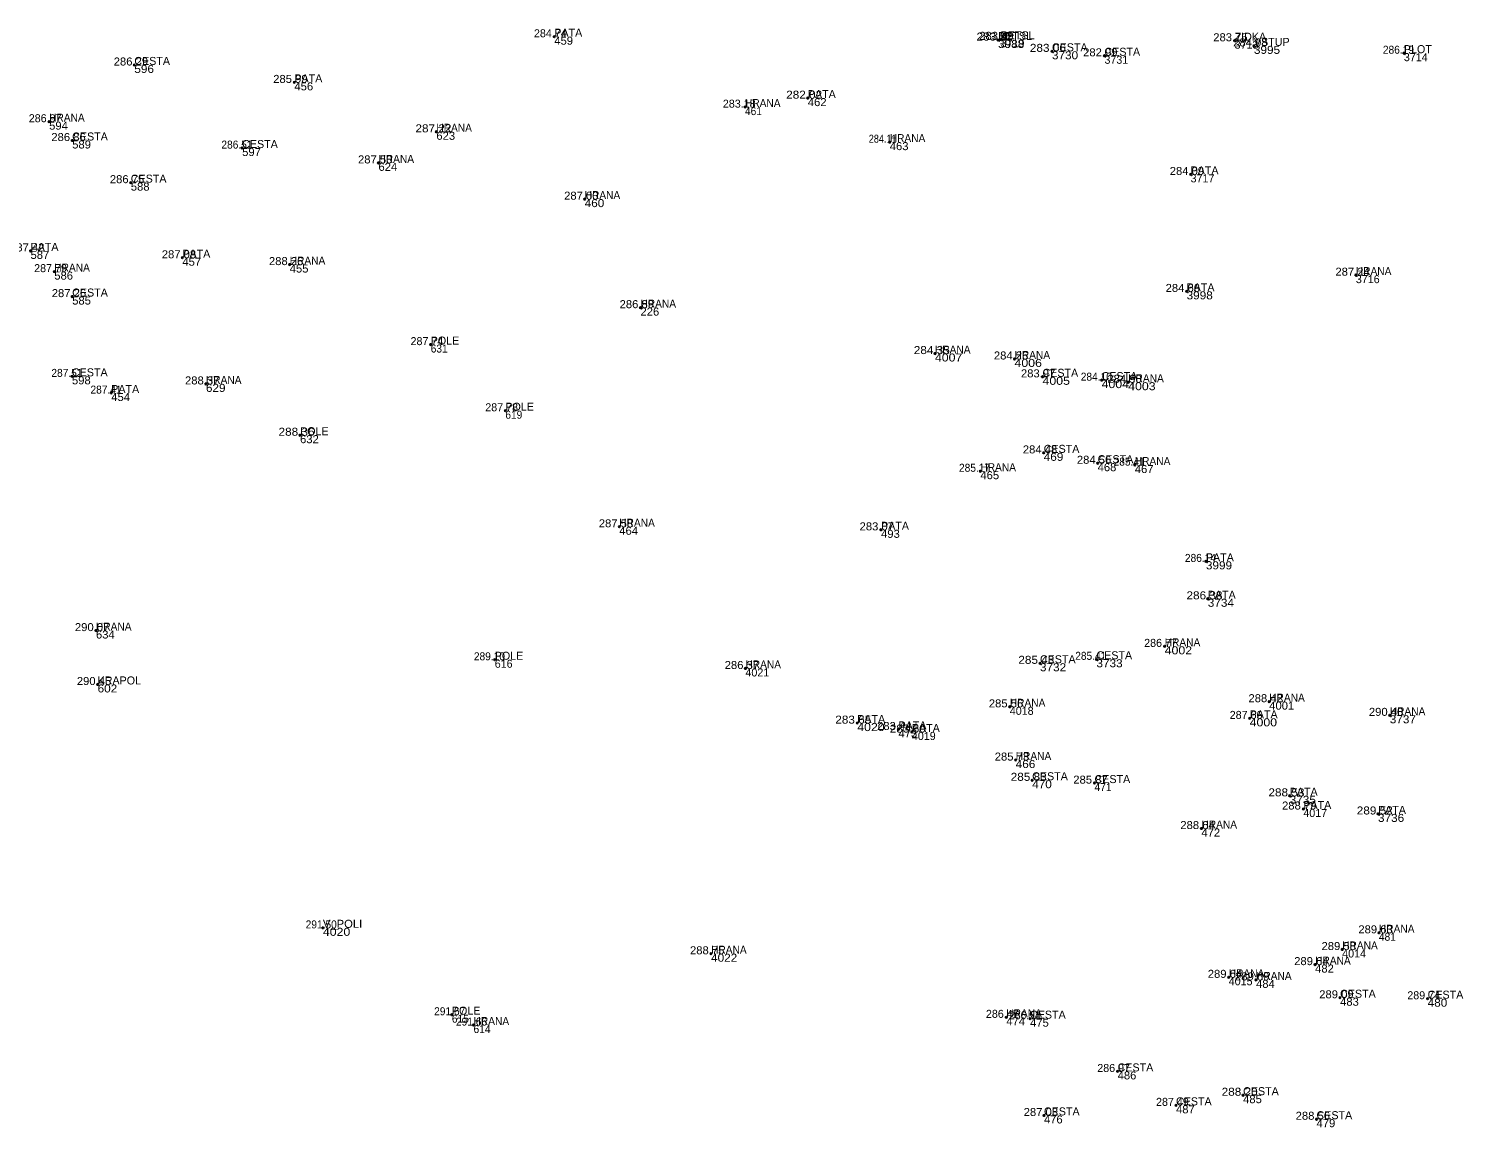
# Model space of a CAD drawing. Extents: x -565336 to -561834, y -1146819 to -1145270.
# Drawn here: x -563681.7 to -563620.8, y -1145851.4 to -1145804.8 of the extents above; entities that cross this region are included whole.
import ezdxf
from ezdxf.enums import TextEntityAlignment as Align

# ---------------------------------------------------------------- set-up
doc = ezdxf.new("R2010")
doc.units = 0
doc.header["$LTSCALE"] = 0.14
doc.header["$PDMODE"] = 32
doc.header["$PDSIZE"] = 0.07
for name, color, linetype in [('40', 7, 'Continuous'), ('43', 7, 'Continuous'), ('44', 7, 'Continuous'), ('45', 7, 'Continuous')]:
    doc.layers.add(name, color=color, linetype=linetype)

msp = doc.modelspace()

# ---------------------------------------------------------------- linework, layer by layer
at = {"layer": '40'}
for p in [(-563659.39, -1145805.09), (-563640.54, -1145805.23), (-563640.43, -1145805.2), (-563630.49, -1145805.26), (-563638.25, -1145805.71), (-563636.02, -1145805.9), (-563629.67, -1145805.48), (-563623.3, -1145805.79), (-563677.23, -1145806.29), (-563670.43, -1145807.03), (-563648.62, -1145807.7), (-563651.29, -1145808.08), (-563680.85, -1145808.7), (-563679.87, -1145809.5), (-563664.4, -1145809.13), (-563645.14, -1145809.57), (-563672.65, -1145809.82), (-563666.86, -1145810.45), (-563677.38, -1145811.29), (-563632.36, -1145810.94), (-563658.1, -1145811.99), (-563681.64, -1145814.19), (-563675.19, -1145814.48), (-563680.63, -1145815.07), (-563670.63, -1145814.77), (-563625.34, -1145815.22), (-563679.87, -1145816.13), (-563632.53, -1145815.91), (-563655.73, -1145816.6), (-563664.64, -1145818.17), (-563643.22, -1145818.55), (-563639.84, -1145818.78), (-563679.88, -1145819.52), (-563674.19, -1145819.84), (-563638.65, -1145819.54), (-563636.14, -1145819.68), (-563635.01, -1145819.77), (-563678.21, -1145820.23), (-563661.47, -1145820.98), (-563670.19, -1145822.02), (-563638.6, -1145822.77), (-563641.29, -1145823.55), (-563636.31, -1145823.21), (-563634.73, -1145823.29), (-563656.63, -1145825.91), (-563645.51, -1145826.04), (-563631.71, -1145827.38), (-563631.63, -1145828.97), (-563678.86, -1145830.32), (-563661.92, -1145831.56), (-563636.36, -1145831.54), (-563633.46, -1145830.99), (-563651.27, -1145831.93), (-563638.76, -1145831.71), (-563678.79, -1145832.61), (-563629.02, -1145833.34), (-563640.04, -1145833.56), (-563623.9, -1145833.92), (-563646.52, -1145834.25), (-563644.77, -1145834.52), (-563644.2, -1145834.63), (-563629.85, -1145834.05), (-563639.79, -1145835.82), (-563639.09, -1145836.68), (-563636.44, -1145836.8), (-563628.15, -1145837.34), (-563627.57, -1145837.9), (-563624.4, -1145838.11), (-563631.9, -1145838.73), (-563669.22, -1145842.95), (-563624.36, -1145843.16), (-563652.73, -1145844.05), (-563625.92, -1145843.87), (-563627.07, -1145844.51), (-563630.74, -1145845.05), (-563629.58, -1145845.16), (-563626.01, -1145845.92), (-563622.29, -1145845.96), (-563663.74, -1145846.64), (-563640.19, -1145846.75), (-563639.18, -1145846.81), (-563662.82, -1145847.08), (-563635.46, -1145849.05), (-563630.13, -1145850.06), (-563638.59, -1145850.92), (-563632.98, -1145850.49), (-563627.01, -1145851.08)]:
    msp.add_point(p, dxfattribs=at)

# ---------------------------------------------------------------- texts
at = {"layer": '43'}
for s, width, p in [('459', 1.05, (-563659.39, -1145805.43)), ('3988', 1.1, (-563640.54, -1145805.57)), ('3730', 1.1, (-563638.25, -1145806.05)), ('3995', 1.1, (-563629.67, -1145805.82)), ('596', 1.1, (-563677.23, -1145806.63)), ('456', 1.05, (-563670.43, -1145807.37)), ('462', 1.05, (-563648.62, -1145808.04)), ('461', 0.95, (-563651.29, -1145808.42)), ('594', 1.05, (-563680.85, -1145809.04)), ('589', 1.05, (-563679.87, -1145809.84)), ('623', 1.05, (-563664.4, -1145809.47)), ('463', 1.05, (-563645.14, -1145809.91)), ('597', 1.05, (-563672.65, -1145810.16)), ('624', 1.05, (-563666.86, -1145810.79)), ('588', 1.05, (-563677.38, -1145811.63)), ('460', 1.1, (-563658.1, -1145812.33)), ('587', 1.05, (-563681.64, -1145814.53)), ('457', 1.05, (-563675.19, -1145814.82)), ('586', 1.05, (-563680.63, -1145815.41)), ('455', 1.05, (-563670.63, -1145815.11)), ('585', 1.05, (-563679.87, -1145816.47)), ('3998', 1.1, (-563632.53, -1145816.25)), ('226', 1.05, (-563655.73, -1145816.94)), ('631', 0.95, (-563664.64, -1145818.51)), ('4007', 1.15, (-563643.22, -1145818.89)), ('4006', 1.15, (-563639.84, -1145819.12)), ('598', 1.05, (-563679.88, -1145819.86)), ('629', 1.1, (-563674.19, -1145820.18)), ('4005', 1.15, (-563638.65, -1145819.88)), ('4004', 1.15, (-563636.14, -1145820.02)), ('4003', 1.15, (-563635.01, -1145820.11)), ('454', 1.05, (-563678.21, -1145820.57)), ('619', 0.95, (-563661.47, -1145821.32)), ('632', 1.05, (-563670.19, -1145822.36)), ('469', 1.1, (-563638.6, -1145823.11)), ('465', 1.05, (-563641.29, -1145823.89)), ('468', 1.05, (-563636.31, -1145823.55)), ('467', 1.05, (-563634.73, -1145823.63)), ('464', 1.05, (-563656.63, -1145826.25)), ('493', 1.05, (-563645.51, -1145826.38)), ('3999', 1.1, (-563631.71, -1145827.72)), ('3734', 1.1, (-563631.63, -1145829.31)), ('634', 1.05, (-563678.86, -1145830.66)), ('3733', 1.1, (-563636.36, -1145831.88)), ('4002', 1.15, (-563633.46, -1145831.33)), ('3732', 1.1, (-563638.76, -1145832.05)), ('602', 1.1, (-563678.79, -1145832.95)), ('4001', 1.05, (-563629.02, -1145833.68)), ('3737', 1.1, (-563623.9, -1145834.26)), ('4020', 1.15, (-563646.52, -1145834.59)), ('473', 1.05, (-563644.77, -1145834.86)), ('4000', 1.15, (-563629.85, -1145834.39)), ('466', 1.1, (-563639.79, -1145836.16)), ('470', 1.1, (-563639.09, -1145837.02)), ('471', 0.95, (-563636.44, -1145837.14)), ('3735', 1.1, (-563628.15, -1145837.68)), ('3736', 1.1, (-563624.4, -1145838.45)), ('472', 1.05, (-563631.9, -1145839.07)), ('4020', 1.15, (-563669.22, -1145843.29)), ('481', 0.95, (-563624.36, -1145843.5)), ('4022', 1.1, (-563652.73, -1145844.39)), ('482', 1.05, (-563627.07, -1145844.85)), ('484', 1.05, (-563629.58, -1145845.5)), ('483', 1.05, (-563626.01, -1145846.26)), ('480', 1.1, (-563622.29, -1145846.3)), ('615', 0.95, (-563663.74, -1145846.98)), ('474', 1.05, (-563640.19, -1145847.09)), ('614', 0.95, (-563662.82, -1145847.42)), ('475', 1.05, (-563639.18, -1145847.15)), ('486', 1.05, (-563635.46, -1145849.39)), ('485', 1.05, (-563630.13, -1145850.4)), ('476', 1.05, (-563638.59, -1145851.26)), ('487', 1.05, (-563632.98, -1145850.83)), ('479', 1.05, (-563627.01, -1145851.42))]:
    msp.add_text(s, height=0.34, dxfattribs=dict(at, width=width)).set_placement(p)
for s, p in [('3719', (-563640.43, -1145805.54)), ('3713', (-563630.49, -1145805.6)), ('3731', (-563636.02, -1145806.24)), ('3714', (-563623.3, -1145806.13)), ('3717', (-563632.36, -1145811.28)), ('3716', (-563625.34, -1145815.56)), ('616', (-563661.92, -1145831.9)), ('4021', (-563651.27, -1145832.27)), ('4018', (-563640.04, -1145833.9)), ('4019', (-563644.2, -1145834.97)), ('4017', (-563627.57, -1145838.24)), ('4014', (-563625.92, -1145844.21)), ('4015', (-563630.74, -1145845.39))]:
    msp.add_text(s, height=0.34, dxfattribs=at).set_placement(p)
at = {"layer": '44'}
for s, p in [('284.74', (-563659.559, -1145805.114)), ('283.18', (-563651.534, -1145808.104)), ('286.97', (-563681.019, -1145808.724)), ('287.79', (-563680.791, -1145815.094)), ('287.74', (-563664.801, -1145818.194)), ('287.78', (-563661.627, -1145821.004)), ('286.77', (-563633.637, -1145831.014)), ('287.66', (-563630.0025, -1145834.074)), ('289.74', (-563622.459, -1145845.984)), ('286.47', (-563640.359, -1145846.774)), ('286.97', (-563635.629, -1145849.074)), ('287.49', (-563633.1325, -1145850.514))]:
    msp.add_text(s, height=0.34, dxfattribs=at).set_placement(p, align=Align.CENTER)
for s, width, p in [('283.22', 1.1, (-563640.689, -1145805.254)), ('283.49', 1.05, (-563640.608, -1145805.224)), ('283.75', 1.05, (-563630.667, -1145805.284)), ('284.08', 1.05, (-563629.8215, -1145805.504)), ('283.06', 1.1, (-563638.423, -1145805.734)), ('282.99', 1.05, (-563636.195, -1145805.924)), ('286.19', 0.95, (-563623.5305, -1145805.814)), ('286.29', 1.05, (-563677.376, -1145806.314)), ('285.99', 1.05, (-563670.6, -1145807.054)), ('282.02', 1.1, (-563648.775, -1145807.724)), ('287.22', 1.1, (-563664.5235, -1145809.154)), ('286.86', 1.05, (-563680.0255, -1145809.524)), ('286.51', 0.95, (-563672.871, -1145809.844)), ('284.11', 0.85, (-563645.44, -1145809.594)), ('287.50', 1.05, (-563666.998, -1145810.474)), ('284.09', 1.05, (-563632.5155, -1145810.964)), ('286.75', 1.05, (-563677.5395, -1145811.314)), ('287.00', 1.05, (-563658.242, -1145812.014)), ('287.42', 1.05, (-563681.778, -1145814.214)), ('287.08', 1.05, (-563675.3335, -1145814.504)), ('288.26', 1.05, (-563670.7815, -1145814.794)), ('287.24', 1.05, (-563625.478, -1145815.244)), ('284.66', 1.05, (-563632.6905, -1145815.934)), ('287.26', 1.05, (-563680.008, -1145816.154)), ('286.89', 1.05, (-563655.8855, -1145816.624)), ('284.35', 1.1, (-563643.354, -1145818.574)), ('284.26', 1.05, (-563639.986, -1145818.804)), ('287.51', 0.95, (-563680.093, -1145819.544)), ('283.97', 1.05, (-563638.8365, -1145819.564)), ('284.10', 0.95, (-563636.365, -1145819.704)), ('287.41', 0.95, (-563678.4325, -1145820.254)), ('288.37', 1.05, (-563674.347, -1145819.864)), ('284.90', 1.05, (-563635.1655, -1145819.794)), ('288.36', 1.1, (-563670.339, -1145822.044)), ('284.48', 1.05, (-563638.7565, -1145822.794)), ('284.56', 1.05, (-563636.4615, -1145823.234)), ('285.41', 0.95, (-563634.97, -1145823.314)), ('285.17', 0.95, (-563641.538, -1145823.574)), ('287.58', 1.05, (-563656.7695, -1145825.934)), ('283.07', 1.05, (-563645.691, -1145826.064)), ('286.14', 0.95, (-563631.9405, -1145827.404)), ('286.38', 1.1, (-563631.7695, -1145828.994)), ('290.07', 1.05, (-563679.0235, -1145830.344)), ('289.10', 0.95, (-563662.145, -1145831.584)), ('285.43', 1.1, (-563638.913, -1145831.734)), ('285.41', 0.95, (-563636.6, -1145831.564)), ('286.37', 1.05, (-563651.4215, -1145831.954)), ('290.45', 1.05, (-563678.9415, -1145832.634)), ('285.56', 1.05, (-563640.201, -1145833.584)), ('288.42', 1.05, (-563629.1715, -1145833.364)), ('283.65', 1.1, (-563646.689, -1145834.274)), ('290.40', 1.05, (-563624.0555, -1145833.944)), ('283.44', 1.05, (-563644.948, -1145834.544)), ('283.60', 1.1, (-563644.373, -1145834.654)), ('285.73', 1.05, (-563639.951, -1145835.844)), ('285.83', 1.1, (-563639.2375, -1145836.704)), ('285.87', 1.05, (-563636.613, -1145836.824)), ('288.53', 1.1, (-563628.2895, -1145837.364)), ('288.79', 1.05, (-563627.7445, -1145837.924)), ('289.52', 1.1, (-563624.5365, -1145838.134)), ('288.64', 1.05, (-563632.066, -1145838.754)), ('291.50', 0.95, (-563669.291, -1145842.974)), ('289.63', 1.05, (-563624.5035, -1145843.184)), ('288.75', 1.05, (-563652.895, -1145844.074)), ('289.58', 1.05, (-563626.0675, -1145843.894)), ('289.64', 1.05, (-563627.2305, -1145844.534)), ('289.64', 1.05, (-563630.9005, -1145845.074)), ('289.69', 1.05, (-563629.7405, -1145845.184)), ('289.09', 1.05, (-563626.1655, -1145845.944)), ('291.67', 0.95, (-563663.834, -1145846.664)), ('291.66', 0.95, (-563662.9055, -1145847.104)), ('286.51', 0.95, (-563639.401, -1145846.834)), ('288.20', 1.1, (-563630.276, -1145850.084)), ('287.03', 1.05, (-563638.72, -1145850.944)), ('288.56', 1.05, (-563627.167, -1145851.104))]:
    msp.add_text(s, height=0.34, dxfattribs=dict(at, width=width)).set_placement(p, align=Align.CENTER)
at = {"layer": '45'}
for s, p in [('PATA', (-563659.39, -1145805.09)), ('BETSL', (-563640.54, -1145805.23)), ('BETSL', (-563640.43, -1145805.2)), ('ZIDKA', (-563630.49, -1145805.26)), ('VSTUP', (-563629.67, -1145805.48)), ('CESTA', (-563677.23, -1145806.29)), ('CESTA', (-563638.25, -1145805.71)), ('CESTA', (-563636.02, -1145805.9)), ('PLOT', (-563623.3, -1145805.79)), ('PATA', (-563670.43, -1145807.03)), ('PATA', (-563648.62, -1145807.7)), ('CESTA', (-563679.87, -1145809.5)), ('CESTA', (-563672.65, -1145809.82)), ('PATA', (-563632.36, -1145810.94)), ('CESTA', (-563677.38, -1145811.29)), ('PATA', (-563681.64, -1145814.19)), ('PATA', (-563675.19, -1145814.48)), ('PATA', (-563632.53, -1145815.91)), ('CESTA', (-563679.87, -1145816.13)), ('POLE', (-563664.64, -1145818.17)), ('CESTA', (-563679.88, -1145819.52)), ('CESTA', (-563638.65, -1145819.54)), ('CESTA', (-563636.14, -1145819.68)), ('PATA', (-563678.21, -1145820.23)), ('POLE', (-563661.47, -1145820.98)), ('POLE', (-563670.19, -1145822.02)), ('CESTA', (-563638.6, -1145822.77)), ('CESTA', (-563636.31, -1145823.21)), ('PATA', (-563645.51, -1145826.04)), ('PATA', (-563631.71, -1145827.38)), ('PATA', (-563631.63, -1145828.97)), ('POLE', (-563661.92, -1145831.56)), ('CESTA', (-563638.76, -1145831.71)), ('CESTA', (-563636.36, -1145831.54)), ('KRAPOL', (-563678.79, -1145832.61)), ('PATA', (-563646.52, -1145834.25)), ('PATA', (-563629.85, -1145834.05)), ('PATA', (-563644.77, -1145834.52)), ('PATA', (-563644.2, -1145834.63)), ('CESTA', (-563639.09, -1145836.68)), ('CESTA', (-563636.44, -1145836.8)), ('PATA', (-563628.15, -1145837.34)), ('PATA', (-563627.57, -1145837.9)), ('PATA', (-563624.4, -1145838.11)), ('CESTA', (-563626.01, -1145845.92)), ('CESTA', (-563622.29, -1145845.96)), ('POLE', (-563663.74, -1145846.64)), ('CESTA', (-563639.18, -1145846.81)), ('CESTA', (-563635.46, -1145849.05)), ('CESTA', (-563630.13, -1145850.06)), ('CESTA', (-563632.98, -1145850.49)), ('CESTA', (-563638.59, -1145850.92)), ('CESTA', (-563627.01, -1145851.08))]:
    msp.add_text(s, height=0.34, dxfattribs=at).set_placement(p)
for s, width, p in [('HRANA', 0.95, (-563651.29, -1145808.08)), ('HRANA', 0.95, (-563680.85, -1145808.7)), ('HRANA', 0.95, (-563664.4, -1145809.13)), ('HRANA', 0.95, (-563645.14, -1145809.57)), ('HRANA', 0.95, (-563666.86, -1145810.45)), ('HRANA', 0.95, (-563658.1, -1145811.99)), ('HRANA', 0.95, (-563670.63, -1145814.77)), ('HRANA', 0.95, (-563680.63, -1145815.07)), ('HRANA', 0.95, (-563625.34, -1145815.22)), ('HRANA', 0.95, (-563655.73, -1145816.6)), ('HRANA', 0.95, (-563643.22, -1145818.55)), ('HRANA', 0.95, (-563639.84, -1145818.78)), ('HRANA', 0.95, (-563674.19, -1145819.84)), ('HRANA', 0.95, (-563635.01, -1145819.77)), ('HRANA', 0.95, (-563634.73, -1145823.29)), ('HRANA', 0.95, (-563641.29, -1145823.55)), ('HRANA', 0.95, (-563656.63, -1145825.91)), ('HRANA', 0.95, (-563678.86, -1145830.32)), ('HRANA', 0.95, (-563633.46, -1145830.99)), ('HRANA', 0.95, (-563651.27, -1145831.93)), ('HRANA', 0.95, (-563640.04, -1145833.56)), ('HRANA', 0.95, (-563629.02, -1145833.34)), ('HRANA', 0.95, (-563623.9, -1145833.92)), ('HRANA', 0.95, (-563639.79, -1145835.82)), ('HRANA', 0.95, (-563631.9, -1145838.73)), ('V_POLI', 1.05, (-563669.22, -1145842.95)), ('HRANA', 0.95, (-563624.36, -1145843.16)), ('HRANA', 0.95, (-563652.73, -1145844.05)), ('HRANA', 0.95, (-563625.92, -1145843.87)), ('HRANA', 0.95, (-563627.07, -1145844.51)), ('HRANA', 0.95, (-563630.74, -1145845.05)), ('HRANA', 0.95, (-563629.58, -1145845.16)), ('HRANA', 0.95, (-563662.82, -1145847.08)), ('HRANA', 0.95, (-563640.19, -1145846.75))]:
    msp.add_text(s, height=0.34, dxfattribs=dict(at, width=width)).set_placement(p)

doc.saveas('drawing.dxf')
